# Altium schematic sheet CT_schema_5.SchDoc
size 256 x 245 mm
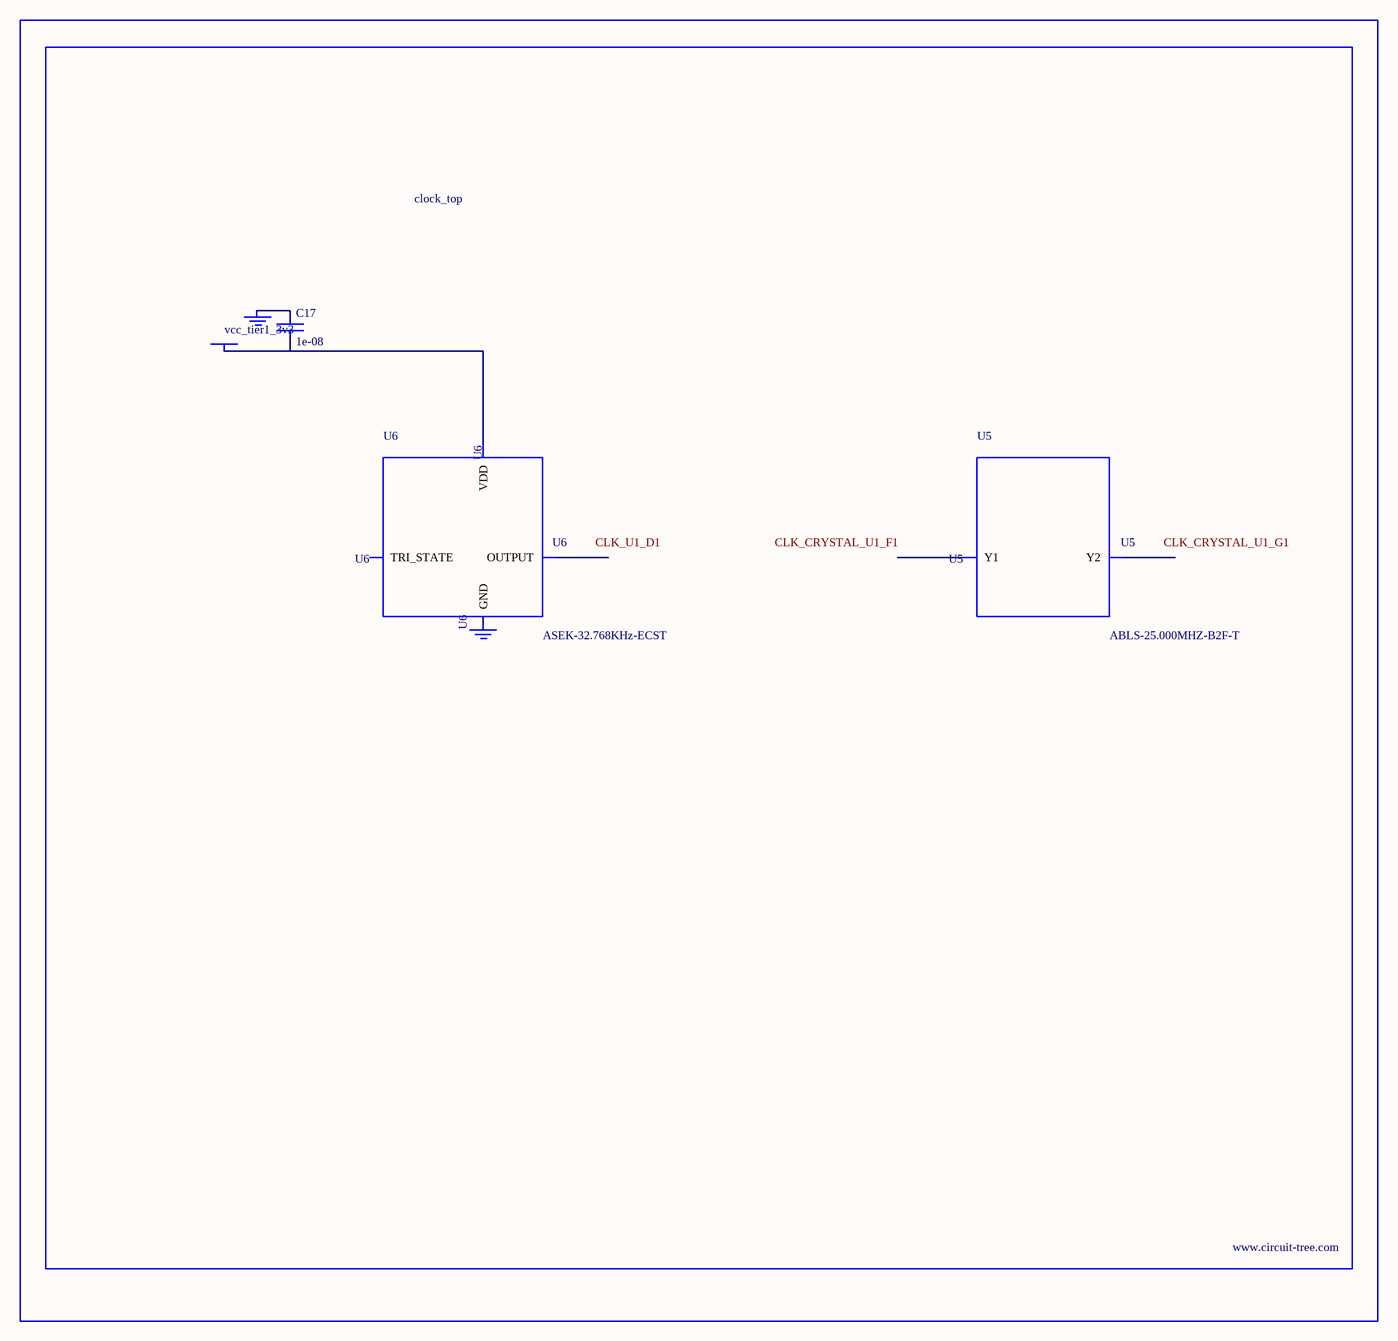
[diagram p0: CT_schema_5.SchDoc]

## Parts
BORDER4  (no value)
C17  1e-08  [C0402]
GND_INSTANCE_4_0  (no value)
GND_INSTANCE_4_1  (no value)
POWER_INSTANCE_4_0  vcc_tier1_3v3
U5  ABLS-25.000MHZ-B2F-T  [ABLS-25.000MHZ-B2F-T]
U6  ASEK-32.768KHz-ECST  [ASEK]

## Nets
NetC17_1: C17.1 GND_INSTANCE_4_0.0(GND)
NetC17_2: C17.2 POWER_INSTANCE_4_0.0(PWR) U6.4(VDD)

Not connected (* = marked no-connect by the designer): GND_INSTANCE_4_1 0(GND); U5 1(Y1) 2(Y2); U6 1(TRI_STATE) 2(GND) 3(OUTPUT)

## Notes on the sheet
- Labels drawn without touching a wire or pin: CLK_CRYSTAL_U1_F1, CLK_CRYSTAL_U1_G1, CLK_U1_D1

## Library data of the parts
BORDER4 = BORDER_PAGE4
C17 = C0402C103K3RAC
GND_INSTANCE_4_0 GND_INSTANCE_4_1 = GND
POWER_INSTANCE_4_0 = PWR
